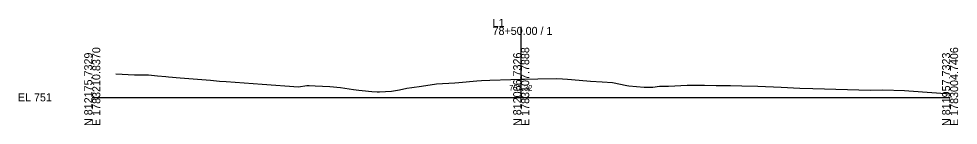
# Model space of a CAD drawing. Extents: x 5574 to 10203, y -10 to 9546.
# Drawn here: x 8574.3 to 8902.8, y 6490.3 to 6527.4 of the extents above; entities that cross this region are included whole.
import ezdxf

# ---------------------------------------------------------------- set-up
doc = ezdxf.new("R2010")
doc.units = 0
for name, color, linetype in [('Exist Cross Section Cell', 7, 'Continuous'), ('Exist XS Center Line Elevation Label', 7, 'Continuous'), ('Exist XS Ground Line', 7, 'Continuous')]:
    doc.layers.add(name, color=color, linetype=linetype)

msp = doc.modelspace()

# ---------------------------------------------------------------- linework, layer by layer
at = {"layer": 'Exist Cross Section Cell'}
for p, q in [((8750, 6500), (8750, 6524.56)), ((8600, 6500), (8750, 6500)), ((8750, 6500), (8900, 6500))]:
    msp.add_line(p, q, dxfattribs=at)
at = {"layer": 'Exist XS Ground Line'}
for p, q in [((8608.19, 6508.19), (8614.82, 6507.89)), ((8614.82, 6507.89), (8619.24, 6507.88)), ((8619.24, 6507.88), (8619.66, 6507.83)), ((8619.66, 6507.83), (8622.77, 6507.46)), ((8622.77, 6507.46), (8625.72, 6507.23)), ((8625.72, 6507.23), (8626.65, 6507.19)), ((8626.65, 6507.19), (8630.77, 6506.83)), ((8630.77, 6506.83), (8641.33, 6505.99)), ((8641.33, 6505.99), (8644.5, 6505.64)), ((8644.5, 6505.64), (8646.8, 6505.56)), ((8646.8, 6505.56), (8659.39, 6504.61)), ((8720.42, 6504.66), (8726.82, 6505.04)), ((8726.82, 6505.04), (8728.16, 6505.14)), ((8728.16, 6505.14), (8734.53, 6505.76)), ((8734.53, 6505.76), (8736.12, 6505.85)), ((8736.12, 6505.85), (8739.05, 6506.02)), ((8739.05, 6506.02), (8746.44, 6506.23)), ((8746.44, 6506.23), (8750, 6506.32)), ((8750, 6506.32), (8751.16, 6506.35)), ((8751.16, 6506.35), (8755.82, 6506.42)), ((8755.82, 6506.42), (8762.28, 6506.51)), ((8762.28, 6506.51), (8764.45, 6506.43)), ((8764.45, 6506.43), (8766.25, 6506.37)), ((8766.25, 6506.37), (8770.33, 6506.02)), ((8770.33, 6506.02), (8774.22, 6505.66)), ((8774.22, 6505.66), (8778.36, 6505.38)), ((8778.36, 6505.38), (8781.94, 6505.12)), ((8781.94, 6505.12), (8786.92, 6504.14)), ((8659.39, 6504.61), (8672.1, 6503.61)), ((8672.1, 6503.61), (8675, 6504.11)), ((8675, 6504.11), (8675.8, 6504.18)), ((8675.8, 6504.18), (8677.93, 6504.04)), ((8677.93, 6504.04), (8683.05, 6503.77)), ((8683.05, 6503.77), (8686.82, 6503.45)), ((8686.82, 6503.45), (8691.38, 6502.75)), ((8691.38, 6502.75), (8693.23, 6502.5)), ((8693.23, 6502.5), (8694.41, 6502.4)), ((8694.41, 6502.4), (8697.8, 6502.09)), ((8697.8, 6502.09), (8699.67, 6501.91)), ((8699.67, 6501.91), (8700.45, 6501.93)), ((8700.45, 6501.93), (8704.67, 6502.12)), ((8704.67, 6502.12), (8707.48, 6502.67)), ((8707.48, 6502.67), (8710.04, 6503.21)), ((8710.04, 6503.21), (8711.76, 6503.42)), ((8711.76, 6503.42), (8715.13, 6503.93)), ((8715.13, 6503.93), (8720.42, 6504.66)), ((8786.92, 6504.14), (8787.62, 6504.04)), ((8787.62, 6504.04), (8793.02, 6503.55)), ((8793.02, 6503.55), (8795.37, 6503.55)), ((8795.37, 6503.55), (8796.04, 6503.54)), ((8796.04, 6503.54), (8798.42, 6503.85)), ((8798.42, 6503.85), (8799.85, 6503.9)), ((8799.85, 6503.9), (8801.58, 6503.93)), ((8801.58, 6503.93), (8808.01, 6504.25)), ((8808.01, 6504.25), (8811.2, 6504.23)), ((8811.2, 6504.23), (8814.16, 6504.23)), ((8814.16, 6504.23), (8818.14, 6504.17)), ((8818.14, 6504.17), (8823.16, 6504.11)), ((8823.16, 6504.11), (8827.22, 6504.01)), ((8827.22, 6504.01), (8832.8, 6503.87)), ((8832.8, 6503.87), (8840.92, 6503.56)), ((8840.92, 6503.56), (8847.51, 6503.23)), ((8847.51, 6503.23), (8851.97, 6503.12)), ((8851.97, 6503.12), (8872.21, 6502.52)), ((8872.21, 6502.52), (8876.49, 6502.62)), ((8876.49, 6502.62), (8884.09, 6502.44)), ((8884.09, 6502.44), (8885.54, 6502.31)), ((8885.54, 6502.31), (8900, 6501.25))]:
    msp.add_line(p, q, dxfattribs=at)

# ---------------------------------------------------------------- texts
at = {"layer": 'Exist Cross Section Cell'}
for s, p in [('78+50.00 / 1', (8740, 6521.76)), ('L1', (8740, 6524.56)), ('EL 751', (8574, 6498.6))]:
    msp.add_text(s, height=2.8, dxfattribs=at).set_placement(p)
for s, p in [('N 812175.7329', (8600, 6490)), ('E 1783210.8370', (8602.8, 6490)), ('N 812066.7326', (8750, 6490)), ('E 1783107.7888', (8752.8, 6490)), ('N 811957.7323', (8900, 6490)), ('E 1783004.7406', (8902.8, 6490))]:
    msp.add_text(s, height=2.8, rotation=90, dxfattribs=at).set_placement(p)
at = {"layer": 'Exist XS Center Line Elevation Label'}
msp.add_text('757.32', height=2, dxfattribs=at).set_placement((8745.79, 6502.32))

doc.saveas('drawing.dxf')
